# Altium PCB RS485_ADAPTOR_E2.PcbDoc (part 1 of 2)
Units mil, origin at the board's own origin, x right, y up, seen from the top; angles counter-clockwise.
Board outline 2150 x 1600 mil, 2 copper layers (Top Layer, Bottom Layer), stack 62 mil thick; 112 components, 44 nets, 256 pads, 64 vias.
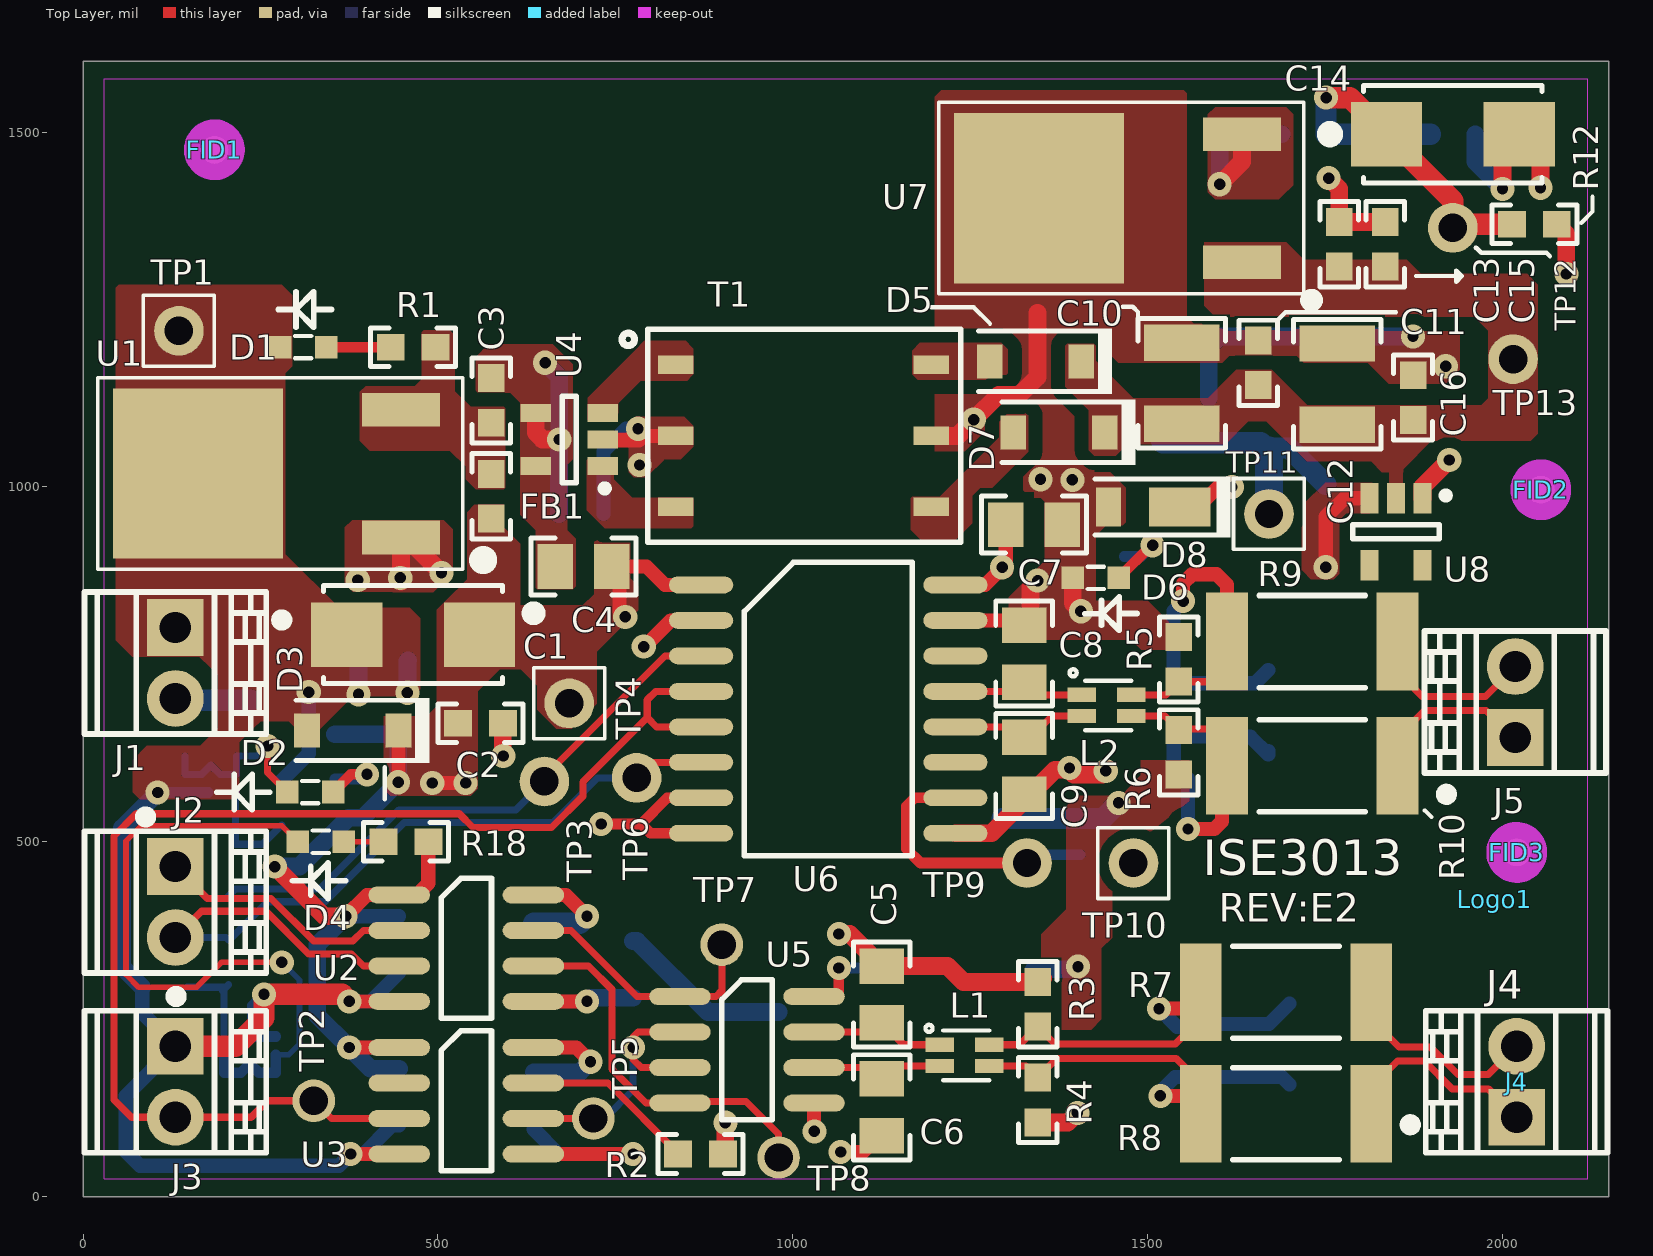
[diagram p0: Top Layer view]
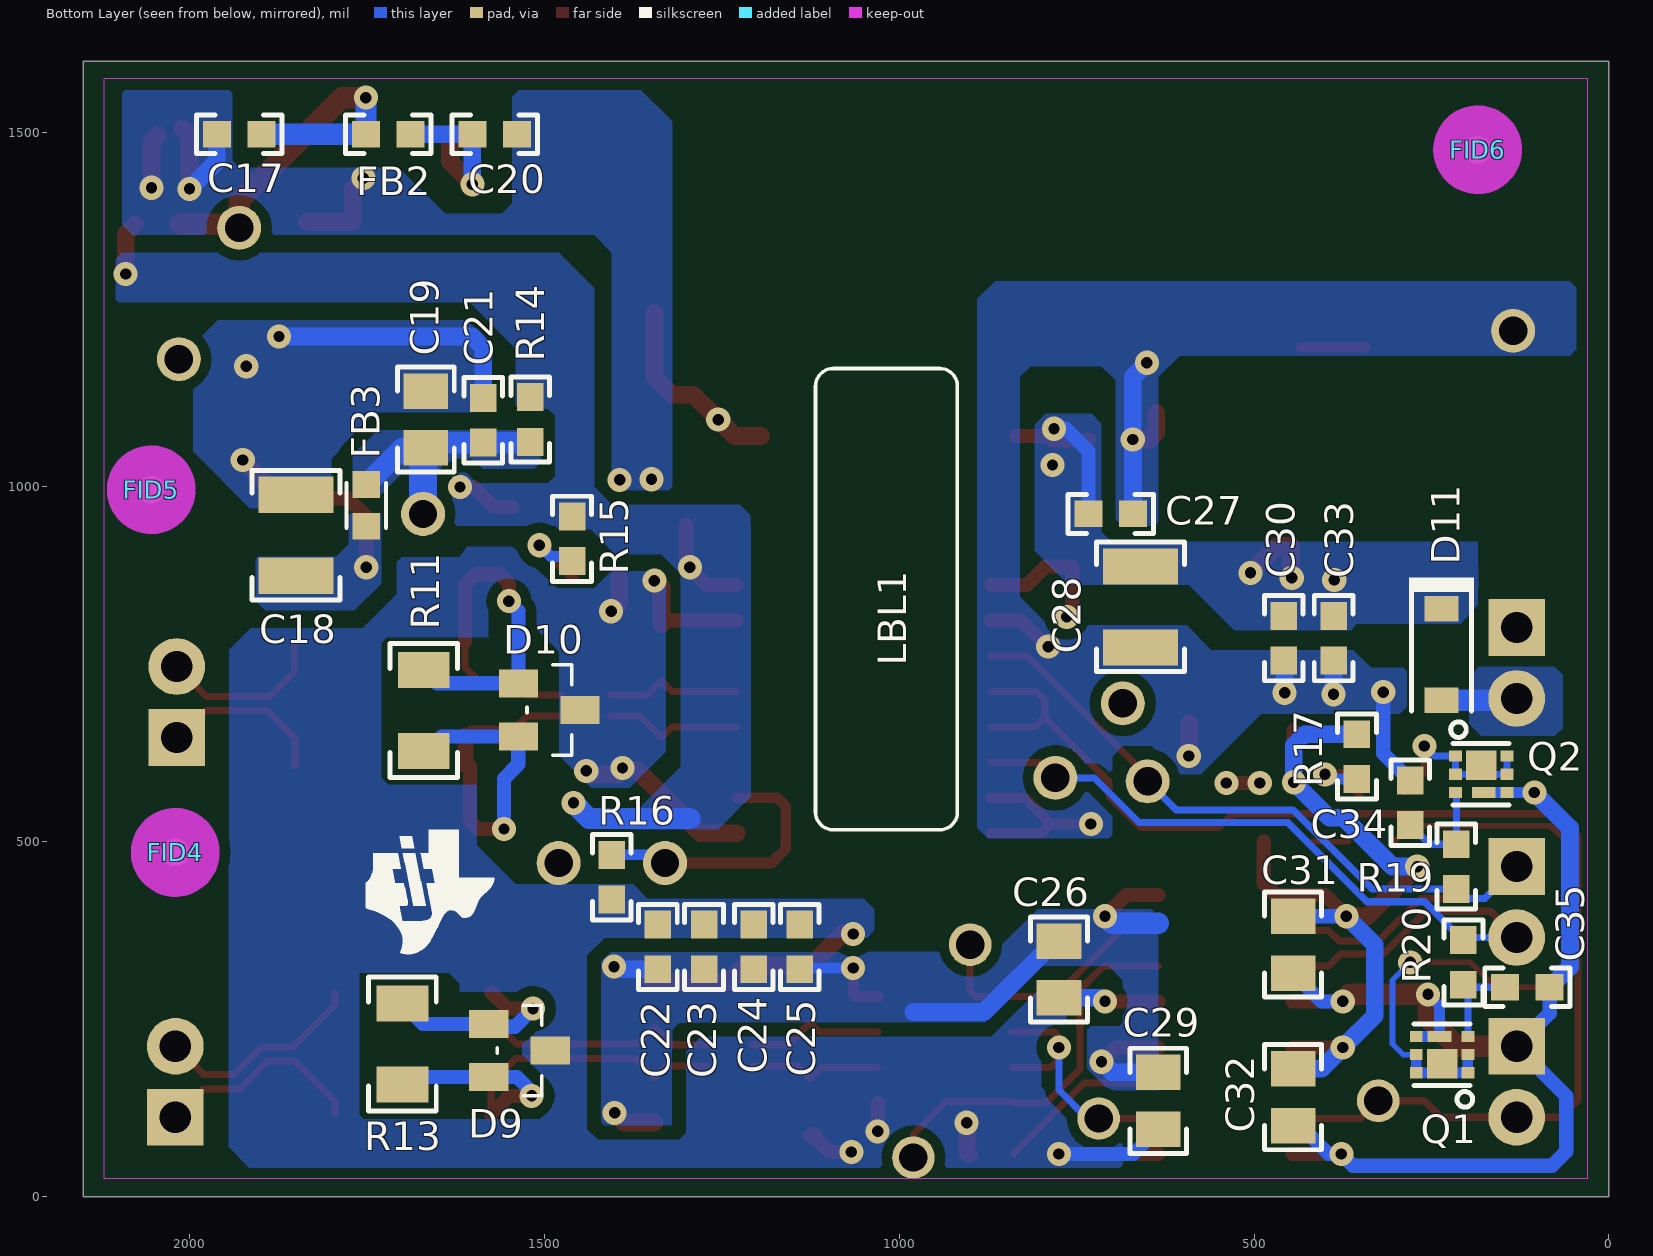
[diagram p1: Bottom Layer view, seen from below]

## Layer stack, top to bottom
Top Layer: signal copper 1.4
Dielectric: core 59.2, FR-4, Dk 4.8
Bottom Layer: signal copper 1.4

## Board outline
0,0 0,1600 2150,1600 2150,0

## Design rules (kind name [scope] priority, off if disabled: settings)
AcuteAngle [All] p1: minimum=4.50000000000000E+0001 checktracksonly=FALSE
AssemblyTestPointUsage [All] p1: valid=2
Clearance Clearance_TH [IsVia vs IsThruPin] p1: gap=10
Clearance "Clearance_SMT to Via" [IsSMTPin vs IsVia] p2: gap=8
Clearance "Clearance_Via to Via" [IsVia vs IsVia] p3: gap=8
Clearance "Clearance_Poly to Poly" [InPolygon vs InPolygon] p4: gap=20
Clearance Clearance_Poly [InPolygon] p5: gap=15
Clearance [All] p6: gap=8
ComponentClearance ComponentClearance_Logo [InComponentClass('Logo')] p1: gap=50 collisioncheckmode=3 verticalgap=10 showdistances=FALSE
ComponentClearance ComponentClearance_ScrewToNut [(HasFootprint('NY PMS 440 0025 PH')) vs (HasFootprint('Keystone_1902C'))] p2: gap=5 collisioncheckmode=3 verticalgap=10 showdistances=FALSE
ComponentClearance ComponentClearance_MountingHoles [InComponentClass('Mounting Holes')] p3: gap=250 collisioncheckmode=3 verticalgap=100000 showdistances=FALSE
ComponentClearance ComponentClearance_SmallPassives [HasFootprint('0201*') or HasFootprint('0402*') or HasFootprint('0508') or HasFootprint('0603*') or HasFootprint('0612') or HasFootprint('0805*') or HasFootprint('0815*') or HasFootprint('0830*') or HasFootprint('1206*') or HasFootprint('1210*') or HasFootprint('1808*') or HasFootprint('1812*') or HasFootprint('1825*') or HasFootprint('2010*') or HasFootprint('2220*') or HasFootprint('2225*') or HasFootprint('2512*') or HasFootprint('2728*') or HasFootprint('3518*') vs HasFootprint('0201*') or HasFootprint('0402*') or HasFootprint('0508') or HasFootprint('0603*') or HasFootprint('0612') or HasFootprint('0805*') or HasFootprint('0815*') or HasFootprint('0830*') or HasFootprint('1206*') or HasFootprint('1210*') or HasFootprint('1808*') or HasFootprint('1812*') or HasFootprint('1825*') or HasFootprint('2010*') or HasFootprint('2220*') or HasFootprint('2225*') or HasFootprint('2512*') or HasFootprint('2728*') or HasFootprint('3518*')] p4: gap=20 collisioncheckmode=3 verticalgap=10 showdistances=FALSE
ComponentClearance ComponentClearance_THtoSMT [IsThruComponent vs IsSMTComponent] p5: gap=100 collisioncheckmode=3 verticalgap=30 showdistances=FALSE
ComponentClearance ComponentClearance_THtoTH [IsThruComponent vs IsThruComponent] p6: gap=118.11 collisioncheckmode=3 verticalgap=30 showdistances=FALSE
ComponentClearance [All] p7: gap=40 collisioncheckmode=3 verticalgap=10 showdistances=FALSE
DiffPairsRouting [All] p1: maxlimit=100 minlimit=10 mostfreqgap=10 maxuncoupledlength=1000
FabricationTestPointUsage TestPointUsage [All] p1: valid=2 allowmultiple=FALSE
FabricationTestpoint Testpoint [All] p1: side=3 testpointundercomponent=TRUE minsize=40 maxsize=100 preferedsize=60 minholesize=0 maxholesize=40 preferedholesize=32 testpointgrid=1 allowsidetop=TRUE allowsidebottom=TRUE usegrid=TRUE gridtolerance=0.01
FanoutControl Fanout_LCC [IsLCC] p1: bgadir=Out bgaviamode=Centered fanoutstyle=Auto fanoutdirection=Alternating viagrid=1 // Fanout_LCC (Default Rule)
FanoutControl Fanout_BGA [IsBGA] p2: bgadir=Out bgaviamode=Centered fanoutstyle=Auto fanoutdirection=Alternating viagrid=1 // Fanout_BGA (Default Rule)
FanoutControl Fanout_Default [All] p4: bgadir=Out bgaviamode=Centered fanoutstyle=Auto fanoutdirection=Alternating viagrid=1 // Fanout_Default (Default Rule)
FanoutControl Fanout_Small [(CompPinCount < 5)] p5: bgadir=Out bgaviamode=Centered fanoutstyle=Auto fanoutdirection=OutThenIn viagrid=1 // Fanout_Small (Default Rule)
HoleSize [All] p1: absolutevalues=TRUE maxlimit=251 minlimit=8 maxpercent=80.000 minpercent=20.000
MinimumAnnularRing MinimumAnnularRing_ThermalPadVias [IsVia and InAnyComponent] p1: minimumring=5.91
MinimumAnnularRing [All] p2: minimumring=9
MinimumSolderMaskSliver MinimumSolderMaskSliver_Logo [InComponentClass('Logo') vs InComponentClass('Logo')] p1: minsoldermaskwidth=0.7
MinimumSolderMaskSliver [All] p2: minsoldermaskwidth=3.94
PlaneConnect [All] p1: planeconnectstyle=Relief reliefexpansion=10 reliefentries=4 reliefconductorwidth=10 reliefairgap=10
PolygonConnect [All] p1: connectstyle=Direct reliefconductorwidth=20 reliefentries=4 polygonreliefangle="45 Angle" airgapwidth=10
RoutingVias ThermalPadVias [IsVia and InAnyComponent] p1: holewidth=20 width=40 viastyle="Through Hole" minholewidth=16 minwidth=30 maxholewidth=20 maxwidth=40
RoutingVias [All] p2: holewidth=16 width=34 viastyle="Through Hole" minholewidth=12 minwidth=26 maxholewidth=20 maxwidth=40
SMDToCorner [All] p1: distance=30000
SilkToSilkClearance [All] p1: silktosilkclearance=5
SilkscreenOverComponentPads [All] p1: minsilkscreentomaskgap=5
SolderMaskExpansion [All] p1: expansion=2.5
Width [All] p1: maxlimit=200 minlimit=8 preferedwidth=10 checkconnectedcopper=TRUE
14 further rules are at their usual default settings.

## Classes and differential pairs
component class "Page4-DC-DC and Power supply": C10 C11 C12 C13 C14 C15 C16 C17 C18 C19 C20 C21 C27 C28 D5 D6 D7 D8 FB2 FB3 R12 R14 R15 T1 TP11 TP12 TP13 U4 U7 U8
component class "Page3-RS485 Transceivers": C1 C2 C3 C4 C5 C6 C7 C8 C9 C22 C23 C24 C25 C26 C29 C30 C31 C32 C33 C34 C35 D1 D2 D3 D4 D9 D10 D11 FB1 J1 J2 J3 J4 J5 L1 L2 Q1 Q2 R1 R2 R3 R4 R5 R6 R7 R8 R9 R10 R11 R13 R16 R17 R18 R19 R20 TP1 TP2 TP3 TP4 TP5 TP6 TP7 TP8 TP9 TP10 U1 U2 U3 U5 U6
component class AssemblyNote: ZZ1 ZZ2 ZZ3 ZZ4
component class FiducialMark: FID1 FID2 FID3 FID4 FID5 FID6
component class Label: LBL1
component class Page5-Hardware: !PCB1 FID1 FID2 FID3 FID4 FID5 FID6 LBL1 ZZ1 ZZ2 ZZ3 ZZ4

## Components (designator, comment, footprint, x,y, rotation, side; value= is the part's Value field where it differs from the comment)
C1 "293D475X9035C2TE3" 6032-28 465,791.85 r180 top (schematic designator C18)
C2 "C0603C104K5RACTU" 0603 560,666.85 r0 top (schematic designator C21)
C3 "C1608X7R1C105K" 0603 575,1121.85 r90 top (schematic designator C17)
C4 "08055C104KAT2A" 0805_HV 705,887.85 r180 top
C5 "08055A101JAT2A" 0805_HV 1125.5,284.85 r90 top
C6 "08055A101JAT2A" 0805_HV 1125.5,125.85 r270 top
C7 "08055C104KAT2A" 0805_HV 1340,946.85 r0 top (schematic designator C3)
C8 "08055A101JAT2A" 0805_HV 1326,765 r90 top (schematic designator C1)
C9 "08055A101JAT2A" 0805_HV 1326,607 r270 top (schematic designator C2)
C10 "" 1210 1548,1145.85 r90 top (schematic designator C13)
C11 "" 0603 1656,1174.85 r90 top (schematic designator C14)
C12 "" 1210 1767,1144.85 r270 top (schematic designator C22)
C13 "C0603C104K5RACTU" 0603 1770,1341.85 r90 top (schematic designator C26)
C14 "293D475X9035C2TE3" 6032-28 1930,1496.85 r0 top (schematic designator C27)
C15 "C1608X7R1C105K" 0603 1835,1341.85 r90 top (schematic designator C25)
C16 "" 0603 1874,1125.85 r90 top (schematic designator C24)
C17 "C0603C104K5RACTU" 0603 1930,1496.85 r0 bottom (schematic designator C29)
C18 "" 1210 1850,931.85 r270 bottom (schematic designator C23)
C19 "" 0805_HV 1667,1094.85 r270 bottom
C20 "C1608X7R1C105K" 0603 1570,1496.85 r180 bottom (schematic designator C28)
C21 "" 0603 1586,1093.85 r90 bottom (schematic designator C20)
C22 "C0603C106M9PACTU" 0603 1340,351.85 r90 bottom (schematic designator C9)
C23 "06033C104JAT2A" 0603 1275,351.85 r90 bottom (schematic designator C10)
C24 "06033C104JAT2A" 0603 1205,351.85 r90 bottom (schematic designator C11)
C25 "06033C104JAT2A" 0603 1140,351.85 r90 bottom (schematic designator C12)
C26 "08055C104KAT2A" 0805_HV 775,320 r270 bottom (schematic designator C31)
C27 "" 0603 702,961.85 r0 bottom (schematic designator C8)
C28 "" 1210 660,830.85 r90 bottom (schematic designator C7)
C29 "08055C104KAT2A" 0805_HV 635,135 r270 bottom (schematic designator C33)
C30 "C0603C104K5RACTU" 0603 458,786.85 r270 bottom (schematic designator C16)
C31 "08055C104KAT2A" 0805_HV 445,355 r270 bottom (schematic designator C30)
C32 "08055C104KAT2A" 0805_HV 445,140 r270 bottom
C33 "C1608X7R1C105K" 0603 388,786.85 r270 bottom (schematic designator C15)
C34 "06033C104JAT2A" 0603 280,555 r90 bottom (schematic designator C35)
C35 "06033C104JAT2A" 0603 115,295 r180 bottom (schematic designator C34)
D1 "LED_LG L29K-G2J1-24-Z" LED0603AA 310,1196.85 r0 top (schematic designator D6)
D2 "LED_LG L29K-G2J1-24-Z" LED0603AA 320,570 r0 top (schematic designator D11)
D3 "MMSZ5228B-7-F" sod-123 380,656.85 r180 top (schematic designator D8)
D4 "LED_LG L29K-G2J1-24-Z" LED0603AA 335,500 r0 top (schematic designator D10)
D5 "B0520LW-7-F" SOD-123 1342,1176.85 r180 top (schematic designator D3)
D6 "" LED0603AA 1427,871.85 r0 top (schematic designator D9)
D7 "B0520LW-7-F" SOD-123 1375,1076.85 r180 top (schematic designator D4)
D8 "" powerDI123 1495,971.85 r180 top (schematic designator D7)
D9 "SM712.TCT" SM712.TCT 1535,205.85 r270 bottom (schematic designator D2)
D10 "SM712.TCT" SM712.TCT 1493,685.83 r270 bottom (schematic designator D1)
D11 "B0520LW-7-F" SOD-123 236,764 r270 bottom (schematic designator D5)
FB1 "1000 OHM" 0603 575,986.85 r270 top
FB2 "1000 OHM" 0603 1720,1496.85 r0 bottom (schematic designator FB3)
FB3 "" FB0603 1751,973.85 r90 bottom (schematic designator FB2)
FID1 "Fiducial" Fiducial10-20 185,1475 r90 top (schematic designator FID3)
FID2 "Fiducial" Fiducial10-20 2054,996 r90 top (schematic designator FID1)
FID3 "Fiducial" Fiducial10-20 2020,485 r90 top (schematic designator FID2)
FID4 "Fiducial" Fiducial10-30 2020,485 r90 bottom (schematic designator FID5)
FID5 "Fiducial" Fiducial10-30 2054,996 r90 bottom (schematic designator FID6)
FID6 "Fiducial" Fiducial10-30 185,1475 r90 bottom (schematic designator FID4)
J1 "CON-OSTVN02A150" CN2_MTB_P100_PD80_D1.1_S5.54X6.5_STACK 130,751.85 r270 top (schematic designator J7)
J2 "CON-OSTVN02A150" CN2_MTB_P100_PD80_D1.1_S5.54X6.5_STACK 130,415 r270 top (schematic designator J1)
J3 "CON-OSTVN02A150" CN2_MTB_P100_PD80_D1.1_S5.54X6.5_STACK 130,161.85 r270 top
J4 "CON-OSTVN02A150" CN2_MTB_P100_PD80_D1.1_S5.54X6.5_STACK 2020,161.85 r90 top (schematic designator J6)
J5 "CON-OSTVN02A150" CN2_MTB_P100_PD80_D1.1_S5.54X6.5_STACK 2018,696.85 r90 top (schematic designator J2)
L1 "ACM2012-201-2P-T002" IND_0805-4P 1242,199 r0 top (schematic designator L2)
L2 "ACM2012-201-2P-T002" IND_0805-4P 1442,692 r0 top (schematic designator L1)
LBL1 "Size: 0.65\" x 0.20 \"" Label_650x200 1018,841.85 r90 bottom
Logo1 "Texas Instruments" TI_Stacked_SolderMask_Small 1989,419 r0 top
Q1 "CSD17571Q2" SON_CSD17571Q2 235,200 r90 bottom
Q2 "CSD17571Q2" SON_CSD17571Q2 180,595 r270 bottom
R1 "CRCW0603300RJNEA" 0603 465,1196.85 r0 top (schematic designator R7)
R2 "CRCW06034K70JNEA" 0603 870,60 r180 top (schematic designator R15)
R3 "CRCW06034K70JNEA" 0603 1345,271 r270 top (schematic designator R12)
R4 "CRCW06034K70JNEA" 0603 1345,136 r270 top (schematic designator R11)
R5 "CRCW06034K70JNEA" 0603 1544,757 r270 top (schematic designator R10)
R6 "CRCW06034K70JNEA" 0603 1544,626 r270 top (schematic designator R9)
R7 "ERJ-1TYJ100U" 2512M 1695,287.85 r0 top (schematic designator R5)
R8 "ERJ-1TYJ100U" 2512M 1695,116.85 r0 top (schematic designator R4)
R9 "ERJ-1TYJ100U" 2512M 1732,782 r0 top (schematic designator R2)
R10 "ERJ-1TYJ100U" 2512M 1732,607 r0 top (schematic designator R1)
R11 "RC1206FR-07120RL" 1206 1670,685 r90 bottom (schematic designator R3)
R12 "CRCW06030000Z0EA" 0603 2045,1370 r0 top (schematic designator R14)
R13 "RC1206FR-07120RL" 1206 1700,215 r90 bottom (schematic designator R6)
R14 "CRCW06030000Z0EA" 0603 1520,1095 r90 bottom (schematic designator R13)
R15 "" 0603 1461,926.85 r90 bottom (schematic designator R8)
R16 "CRCW06030000Z0EA" 0603 1405,450 r270 bottom (schematic designator R20)
R17 "CRCW0603300RJNEA" 0603 355,620 r90 bottom
R18 "CRCW0603300RJNEA" 0603 455,500 r0 top (schematic designator R16)
R19 "CRCW0603300RJNEA" 0603 215,465 r90 bottom
R20 "CRCW0603300RJNEA" 0603 205,330 r270 bottom (schematic designator R18)
T1 "TRNSFMR 760390014" 760390015 835,1171.85 r0 top
TP1 "TP-040_RND" TP-040_RND#1 135,1220 r0 top (schematic designator TP4)
TP2 "TP-040_RND" TP-040_RND#2 325,135 r90 top (schematic designator TP11)
TP3 "TP-040_RND" TP-040_RND#1 650,585 r90 top (schematic designator TP6)
TP4 "TP-040_RND" TP-040_RND#1 685,695 r180 top (schematic designator TP1)
TP5 "TP-040_RND" TP-040_RND#3 719,110 r90 top (schematic designator TP10)
TP6 "TP-040_RND" TP-040_RND#1 780,590 r90 top (schematic designator TP7)
TP7 "TP-040_RND" TP-040_RND#4 900,355 r90 top (schematic designator TP8)
TP8 "TP-040_RND" TP-040_RND#4 980,55 r90 top (schematic designator TP9)
TP9 "TP-040_RND" TP-040_RND#1 1330,470 r90 top (schematic designator TP12)
TP10 "TP-040_RND" TP-040_RND#1 1480,470 r0 top (schematic designator TP3)
TP11 "" TP-040_RND#1 1671,961.85 r180 top (schematic designator TP2)
TP12 "TP-040_RND" TP-040_RND#1 1930,1365 r0 top (schematic designator TP5)
TP13 "TP-040_RND" TP-040_RND#1 2015,1180 r90 top
U1 "TPS7A6533QKVURQ1" KVU_1 305,1018.85 r90 top (schematic designator U5)
U2 "ISO7221AD" D0008A_N 540,350 r0 top (schematic designator U7)
U3 "ISO7221AD" D0008A_N 540,135 r0 top (schematic designator U8)
U4 "SN6501DBV" DBV0005A_N 685,1066.85 r180 top (schematic designator U3)
U5 "SN65HVD3082ED" D0008A_N 935.5,206.85 r0 top (schematic designator U2)
U6 "ISO3088DW" DW0016A_N 1050,686.85 r0 top (schematic designator U1)
U7 "TPS7A6533QKVURQ1" KVU_1 1490,1406.85 r90 top (schematic designator U6)
U8 "TLV70450DBV" DBV0005A_N 1850,936.85 r270 top (schematic designator U4)
ZZ1 "These assemblies must comply with workmanship standards IPC-A-610 Class 2, unless otherwise specified." AssemblyNote 341,2193.85 r0 top (schematic designator ZZ4)
ZZ2 "This Assembly Note is for PCB labels only" AssemblyNoteLabel 342,2294.85 r0 top (schematic designator ZZ1)
ZZ3 "These assemblies must be clean and free from flux and all contaminants. Use of no clean flux is not acceptable." AssemblyNote 342,2097.85 r0 top
ZZ4 "These assemblies are ESD sensitive, ESD precautions shall be observed." AssemblyNote 341,2017 r0 top

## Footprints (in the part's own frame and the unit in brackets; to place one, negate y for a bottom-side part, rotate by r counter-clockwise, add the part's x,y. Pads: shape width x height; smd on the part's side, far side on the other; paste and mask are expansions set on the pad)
0603 [mm]
  rect 1x0.95 smd: 1(-0.8,0) 2(0.8,0)
  silkscreen extent -1.52,-0.69 1.52,0.69, body extent -0.87,-0.47 0.87,0.47, height 0.85
0805_HV [mil] "0805 with 30mil clearance between pads"
  rect 50x63 smd: 1(-40,0) 2(40,0)
  silkscreen extent -74,-40 74,40, body extent -43,-29 43,29, height 43
1206 [mm] "1206 from SM-752 data"
  rect 1.3x1.85 smd: 1(-1.45,0) 2(1.45,0)
  silkscreen extent -2.4,-1.21 2.4,1.21, body extent -1.7,-0.9 1.7,0.9, height 1.35
1210 [mm]
  rect 1.3x2.7 smd: 1(-1.45,0) 2(1.45,0)
  silkscreen extent -2.32,-1.57 2.32,1.57, body extent -1.7,-1.35 1.7,1.35, height 1.35
2512M [mm] "Chip Resistor, Body 6.3x3.2mm, IPC Low Density"
  rect 1.5x3.5 smd: 1(-3.05,0) 2(3.05,0)
  silkscreen extent -1.9,-1.65 1.9,1.65, body extent -3.22,-1.67 3.22,1.67, height 0.71
6032-28 [mm]
  rect 2.55x2.3 smd: 1(-2.375,0) 2(2.375,0)
  silkscreen extent -4.42,-1.75 3.2,1.75, body extent -3.15,-1.75 3.15,1.75, height 2.8
760390015 [mm]
  rect 1.27x0.66 smd: 1(0,0) 2(0,-2.54) 3(0,-5.08) 4(9.14,-5.08) 5(9.14,-2.54) 6(9.14,0)
  silkscreen extent -1.92,-6.35 10.2,1.27, body extent -1,-6.4 10.2,1.2, height 4.2
AssemblyNote [mil] "Assembly Note"
AssemblyNoteLabel [mil] "Assembly Note for PCB Labels"
CN2_MTB_P100_PD80_D1.1_S5.54X6.5_STACK [mil]
  rect 80x80 / inner round 80 / far side rect 80x80 hole 44: 1(-50,0)
  round 80 hole 44: 2(50,0)
  silkscreen extent -100,-128 100,160
D0008A_N [mm] "SOIC, 8-Leads, Body 4.9x3.9mm, Pitch 1.27mm, IPC Medium Density"
  oval 2.2x0.6 smd: 1(-2.4,1.905) 2(-2.4,0.635) 3(-2.4,-0.635) 4(-2.4,-1.905) 5(2.4,-1.905) 6(2.4,-0.635) 7(2.4,0.635) 8(2.4,1.905)
  silkscreen extent -0.9,-2.5 0.9,2.5, body extent -3,-2.45 3,2.45, height 1.63
DBV0005A_N [mm]
  rect 1.1x0.65 smd: 1(-1.2,0.95) 2(-1.2,0) 3(-1.2,-0.95) 4(1.2,-0.95) 5(1.2,0.95)
  silkscreen extent -1.4,-1.55 0.25,1.88, body extent -1.42,-1.46 1.42,1.46, height 1.08
DW0016A_N [mm] "SOIC, 16-Leads, Body 10.3x7.5mm, Pitch 1.27mm, IPC Medium Density"
  oval 2.3x0.6 smd: 1(-4.55,4.445) 2(-4.55,3.175) 3(-4.55,1.905) 4(-4.55,0.635) 5(-4.55,-0.635) 6(-4.55,-1.905) 7(-4.55,-3.175) 8(-4.55,-4.445) 9(4.55,-4.445) 10(4.55,-3.175) 11(4.55,-1.905) 12(4.55,-0.635) 13(4.55,0.635) 14(4.55,1.905) 15(4.55,3.175) 16(4.55,4.445)
  silkscreen extent -3,-5.25 3,5.25, body extent -5.14,-5.13 5.14,5.13, height 2.5
FB0603 [mm]
  rect 0.95x1 smd: 1(-0.75,0) 2(0.75,0)
  silkscreen extent -0.8,-0.7 0.8,0.7
Fiducial10-20 [mm]
  round 1 smd mask+0.5: 1(0,0)
  Top Layer keep-out circle w1.178: c0,0 r0.5
Fiducial10-30 [mm]
  round 1 smd mask+1: 1(0,0)
  Top Layer keep-out circle w1.678: c0,0 r0.75
IND_0805-4P [mil]
  rect 40x20 smd: 1(-35,15) 2(-35,-15) 3(35,-15) 4(35,15)
  silkscreen extent -55,-35 35,43
KVU_1 [mm]
  rect 1.2x2.8 smd: 1(-2.29,-3.635) 3(2.29,-3.635)
  rect 6.096x6.096 smd: 2(0,3.635)
  silkscreen extent -3.43,-6.63 3.43,7.22
Label_650x200 [mil] "Thermal Transfer Label"
  round 1 on Mech14: 0(0,0)
  silkscreen extent -325,-100 325,100, body extent -326,-101 326,101, height 1
LED0603AA [mil]
  rect 32x32 smd: 1(-32.48,0) 2(32.48,0)
  silkscreen extent -35,-16 40,78
powerDI123 [mm]
  rect 2.2x1.4 smd: 1(-1.275,0)
  rect 0.9x1.4 smd: 2(1.275,0)
  silkscreen extent -3.1,-1.09 1.76,1.09, body extent -2.37,-0.96 1.53,0.97, height 1
SM712.TCT [mm]
  rect 1x1.4 smd: 1(-0.95,-1.1) 2(0.95,-1.1) 3(0,1.1)
  silkscreen extent -1.62,-0.8 1.62,0.8, body extent -1.5,-1.32 1.5,1.32, height 1.08
sod-123 [mm]
  rect 0.915x1.22 smd: 1(-1.637,0) 2(1.637,0)
  silkscreen extent -2.74,-1.17 2.03,1.17, body extent -1.93,-0.9 1.93,0.9, height 1.35
SOD-123 [mm]
  rect 0.915x1.22 smd: 1(-1.637,0) 2(1.637,0)
  silkscreen extent -2.74,-1.17 2.03,1.17, body extent -1.93,-0.9 1.93,0.9, height 1.35
SON_CSD17571Q2 [mm] "SON, MOSFET, N-CH, 30V, 22A, SON 2X2 MM"
  rect 0.4x0.455 smd mask+0.038: 1(-0.65,-0.923) 2(0,-0.923) 5(0,0.923) 6(-0.65,0.923)
  rect 0.4x0.455 smd: 3(0.65,-0.923) 4(0.65,0.923)
  rect 0.4x0.85 smd mask+0.038: 7(0.65,0.096)
  rect 1.05x1.1 smd mask+0.038: 8(-0.325,0)
  silkscreen extent -1.88,-1.09 1.1,1, body extent -1,-1 1,0.97, height 0.85
TI_Stacked_SolderMask_Small [mil]
TP-040_RND#1 [mil]
  round 70 / inner round 62 / far side round 62 hole 40: 1(0,0)
  silkscreen extent -50,-50 50,50
TP-040_RND#2 [mil]
  round 60 hole 40 paste+0: 1(0,0)
TP-040_RND#3 [mil]
  round 60 / inner oval 60x62 / far side round 60 hole 40: 1(0,0)
TP-040_RND#4 [mil]
  round 60 hole 40: 1(0,0)

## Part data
C1 C14: "CAP, TA, 4.7uF, 35V, +/-10%, 1.9 ohm, SMD"
C2 C13 C17 C30: "CAP, CERM, 0.1uF, 50V, +/-10%, X7R, 0603"
C3 C15 C20 C33: "CAP, CERM, 1uF, 16V, +/-10%, X7R, 0603"
C4 C7 C26 C29 C31 C32: "CAP, CERM, 0.1uF, 50V, +/-10%, X7R, 0805"
C5 C6 C8 C9: "CAP, CERM, 100pF, 50V, +/-5%, C0G/NP0, 0805"
C10 C12 C18 C28: library part GMK325AB7106MM-T, "CAP, CERM, 10uF, 35V, +/-20%, X7R, 1210"
C11 C16 C21 C27: library part C0603C104K5RACTU, "CAP, CERM, 0.1uF, 50V, +/-10%, X7R, 0603"
C19: library part C2012X5R1H475K125AB, "CAP, CERM, 4.7uF, 50V, +/-10%, X5R, 0805"
C22: "CAP, CERM, 10uF, 6.3V, +/-20%, X5R, 0603"
C23 C24 C25 C34 C35: "CAP, CERM, 0.1uF, 25V, +/-5%, X7R, 0603"
D1 D2 D4: "LED SmartLED Green 570NM"
D3: library part 1SMB5915BT3G, "DIODE ZENER 3.9V 500MW SOD123"
D5 D7 D11: library part MBR0520LT1G, "Diode, Schottky, 20V, 0.5A, SOD-123"
D6: library part "LED_LG L29K-G2J1-24-Z", "LED SmartLED Green 570NM"
D8: library part DFLZ6V2-7, "Diode, Zener, 6.2V, 1W, PowerDI123"
D9 D10: "IC TVS ASYMM RS-485V 7/12V SOT23"
FB1 FB2 FB3: library part MMZ1608B102C, "FERRITE CHIP 1000 OHM 300MA 0603"
FID1 FID2 FID3 FID4 FID5 FID6: "Fiducial mark.  There is nothing to buy or mount."
J1: "CONN TERM BLOCK 2.54MM 2POS PCB"
J2 J3 J4 J5: "Terminal Block, 4x1, 2.54mm, TH"
L1 L2: library part IND_ACM2012_SERIES, "CHOKE COMM MODE 200 OHM .35A SMD"
LBL1: library part THT-14-423-10, "Thermal Transfer Printable Labels, 0.650\" W x 0.200\" H - 10,000 per roll"
Logo1: library part TI_Logo, "Texas Instrument Corporate Signature"
Q1 Q2: "MOSFET, N-CH, 30V, 22A, SON 2X2 MM"
R1 R17 R18 R19 R20: "RES, 300 ohm, 5%, 0.1W, 0603"
R2 R3 R4 R5 R6: "RES, 4.7k ohm, 5%, 0.1W, 0603"
R7 R8 R9 R10: "RES, 10 ohm, 5%, 1W, 2512"
R11 R13: "RES, 120 ohm, 1%, 0.25W, 1206"
R12 R14 R16: "RES, 0 ohm, 5%, 0.1W, 0603"
R15: library part CRCW06033K90JNEA, "RES, 3.9k ohm, 5%, 0.1W, 0603"
T1: library part "TRNSFMR 760390015", "Transformer 475uH SMD"
TP1 TP2 TP3 TP4 TP5 TP6 TP7 TP8 TP9 TP10 TP12 TP13: "Test Point, O.040 Hole"
TP11: library part TP-040_RND, "Test Point, O.040 Hole"
U1 U7: "IC, 300-mA 40-V LOW-DROPOUT REGULATOR WITH 25-uA QUIESCENT CURRENT"
U2 U3: "1 Mbps Dual Channels, 1 / 1, Digital Isolator, 3.3 V / 5 V, -40 to +125 degC, 8-pin SOIC (D), Green (RoHS & no Sb/Br)"
U4: "Transformer Driver for Isolated Power Supplies, DBV0005A"
U5: "IC, RS485 TRANSCEIVER LP, 8-SOIC"
U6: "Isolated RS-485 Transceiver, 20 Mbps, 5 V, Half Duplex, -40 to 85 degC, 16-pin SOIC (DW)"
U8: "Regulator, LDO, 5V, 0.15A, SOT23-5"
ZZ1 ZZ3 ZZ4: library part AssemblyNote
ZZ2: library part AssemblyNoteLabel

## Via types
v1: diameter 34, hole 16, Top Layer to Bottom Layer, tented both sides, 64 vias

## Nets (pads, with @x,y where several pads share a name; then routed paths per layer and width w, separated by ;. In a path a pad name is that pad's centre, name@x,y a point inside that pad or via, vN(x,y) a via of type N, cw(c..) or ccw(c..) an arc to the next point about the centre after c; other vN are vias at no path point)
+5.0V_VDC: C7.1 C22.1 C23.1 C24.1 C25.1 C26.1 C29.1 D8.1 R4.2 R6.2 R12.2 R14.2 R15.2 U2.8 U3.8 U5.8 U6.16 | length 1330.7
  Top Layer w15: U5.8@1029.98,281.85 1061.85,281.85 1065,285 v1(1065,322)
  Top Layer w20: U3.8@634.49,210 695,210 v1(715,190) ; U2.8@634.49,425 680,425 v1(710,395) ; U6.16@1229.13,861.85 1271,861.85 1295.5,886.35 1300,881.85 C7.1@1300,946.85 ; D8.1@1545.2,971.85 1571,971.85 1599,999.85 v1(1619,999.85)
  Top Layer w25: R4.2@1345,104.5 1387.5,104.5 v1(1401,118) ; R12.2@2076.5,1370 2090,1356.5 v1(2090,1300)
  Bottom Layer w15: v1(1065,322) 1138.35,322 C25.1@1140,320.35
  Bottom Layer w25: C29.1@635,175 700,175 v1(715,190) ; C26.1@775,360 780.49,360 880.49,260 980,260 ; C22.1@1340,320.35 v1@1389.65,320.35
  Bottom Layer w30: 635,385 700,385 v1(710,395) ; 1295,532.85 1437,532.85 v1(1459,554.85)
  other v1: 1402,324 1295,886.85
+5V: C27.2 C28.2 C30.1 C33.1 D11.1 T1.2 U1.1 U4.2 | length 378.2
  Top Layer w20: U4.2@732.24,1066.85 733.24,1065.85 783,1065.85 789,1071.85 T1.2@835,1071.85
  Top Layer w25: v1@448.11,866.74 448.11,916.69 467.16,916.69 v1(505,878.85)
  Bottom Layer w20: C27.2@733.5,961.85 733.5,1050.35 765,1081.85 v1(782,1081.85)
  other v1: 387,868.85 447,871.85 784,1030.85
+6V_VDC: C10.1 C11.1 C12.2 C13.1 C15.1 C16.1 D5.1 D7.1 TP13.1 U7.1 U8.2
DGND: C1.2 C2.2 C3.2 C4.2 C27.1 C28.1 C30.2 C31.2 C32.2 C33.2 C34.2 C35.2 D1.1 D3.2 J1.1 J3.1 Q1.4 Q1.7 Q2.4 Q2.7 TP1.1 U1.2 U2.4 U3.4 U4.4 U4.5 U6.2 U6.7 U6.8 | length 2609.5
  Top Layer w15: v1(730,525) 786.42,525 ; U6.8@870.87,511.85 799.57,511.85 786.42,525 ; U6.7@870.87,561.85 823.27,561.85 786.42,525
  Top Layer w20: v1(375,275) U2.4@445.51,275 ; v1(377,60) U3.4@445.51,60 ; v1(790,774.85) 790,773.85 828,811.85 U6.2@870.87,811.85
  Top Layer w25: C2.2@591.5,666.85 591.5,621.35 v1(592,620.85) ; U4.4@637.76,1104.25 637.76,1076.61 647.51,1066.85 v1(671,1066.85)
  Top Layer w30: J3.1@130,211.85 214.85,211.85 255,252 v1(255,285) 365,285 v1(375,275)
  Bottom Layer w15: v1(105,569.41) Q2.4@143.68,569.41 Q2.7@176.22,569.41 ; v1(255,285) 238.78,268.78 Q1.7@238.78,225.59 Q1.4@271.32,225.59
  Bottom Layer w20: C35.2@83.5,295 83.5,258.35 J3.1@130,211.85 60,141.85 60,63.5 80,43.5 360.5,43.5 v1(377,60) 395,60 435,100 C32.2@445,100 ; C34.2@280,586.5 318,624.5 v1(318,710.85) ; v1(375,275) 405,275 C31.2@445,315
  Bottom Layer w25: C35.2@83.5,295 55,323.5 55,519.41 v1(105,569.41) ; v1(388,707.85) C33.2@388,755.35 ; v1(457,709.85) 457,754.35 C30.2@458,755.35 ; v1(651,1174.85) 671,1154.85 v1(671,1066.85) v1@670.5,1066.35 ; v1@669,1064.85 v1@670.5,1066.35 ; C27.1@670.5,961.85 v1@670.5,1066.35
DIR: J3.2 TP2.1 U3.3 U6.4 U6.5 | length 1839.3
  Top Layer w10: U3.3@445.51,110 350,110 TP2.1@325,135 260,135 236.85,111.85 J3.2@130,111.85 68.15,111.85 43.5,136.5 43.5,507.91 75,539.41 530,539.41 549.41,520 660.15,520 704.15,564 704.15,584.15 795,675 ; U6.5@870.87,661.85 808.15,661.85 795,675 ; U6.4@870.87,711.85 806.85,711.85 795,700 795,675
DVCC: C1.1 C2.1 C4.1 C31.1 C32.1 D3.1 FB1.2 R17.2 R18.2 TP4.1 U2.1 U3.1 U6.1 | length 1463.8
  Top Layer w20: v1(370,395) 400,425 U2.1@445.51,425 470,425 486.5,441.5 R18.2@486.5,500 ; v1(375,210) U3.1@445.51,210 ; v1(444,583.85) 444.47,584.32 D3.1@444.47,656.85 ; v1(492,582.85) v1(539,582.85) ; v1(764,816.85) 756,824.85 756,887.85 794,887.85 820,861.85 U6.1@870.87,861.85
  Top Layer w25: v1(270,465) 340,395 v1(370,395)
  Bottom Layer w20: v1(370,395) C31.1@445,395 ; v1@491,583.85 v1(492,582.85)
  Bottom Layer w25: v1(270,465) 305,465 373.93,533.93 394.07,533.93 v1(444,583.85) 444,636 428.5,651.5 R17.2@355,651.5 ; v1(370,395) 330,355 330,255 v1(375,210) 405,180 C32.1@445,180
GND_VDC: C5.2 C6.2 C7.2 C8.2 C9.2 C10.2 C11.2 C12.1 C13.2 C14.2 C15.2 C16.2 C17.2 C18.1 C19.1 C20.2 C21.2 C22.2 C23.2 C24.2 C25.2 C26.2 C29.2 D6.1 D8.2 D9.3 D10.3 R2.1 R3.1 R5.1 R16.2 T1.5 TP10.1 U2.5 U3.5 U5.5 U6.9 U6.15 U7.2 U8.1 | length 2482
  Top Layer w20: U3.5@634.49,60 v1(775,60) ; U2.5@634.49,275 v1(710,275) ; U5.5@1029.98,131.85 1029.98,92.36 v1(1030.5,91.85) ; v1(1067.5,62.85) 1098.5,62.85 1121.5,85.85 C6.2@1125.5,85.85 ; U6.15@1229.13,811.85 1330,811.85 C8.2@1335,806.85
  Top Layer w25: R2.1@901.5,60 905,63.5 v1(905,104) ; v1(1065,370) 1080.35,370 C5.2@1125.5,324.85 1218.15,324.85 1240.5,302.5 R3.1@1345,302.5 ; C6.2@1120,85.85 C6.2@1121.5,85.85 ; T1.5@1194.84,1071.85 1232,1071.85 v1(1255,1094.85) 1290.15,1130 1320,1130 1345,1155 1345,1245 ; U6.9@1229.13,511.85 1280,511.85 1335,566.85 1369.5,601.35 1387.5,601.35 v1(1390,603.85) ; C8.2@1335,806.85 1335,857.85 v1(1345,867.85) v1@1345,868.85 ; R3.1@1345,307.5 R3.1@1352.47,307.5 ; D6.1@1394.52,871.85 1394.52,836.33 v1(1406,824.85) ; v1@1396,594.85 1436,594.85 v1(1441,599.85) ; v1(1755,1435) 1770,1420 C13.2@1770,1373.35 C15.2@1835,1373.35 ; U8.1@1887.4,984.09 1887.4,1000.25 v1(1925,1037.85) ; v1(2000,1420) 2000,1495 C14.2@2010,1505 ; C14.2@2045,1495 2053.5,1486.5 v1(2053.5,1421.5)
  Bottom Layer w20: C29.2@635,95 670,60 v1(775,60)
  Bottom Layer w25: v1(710,275) 715,280 C26.2@775,280 ; v1@1405,823.85 v1(1406,824.85) ; C21.2@1586,1125.35 1586,1196 1601.85,1211.85 v1(1874,1211.85) ; C17.2@1961.5,1496.85 1961.5,1458.5 v1(2000,1420)
  other v1: 1394,1009.85 1349,1010.85 1920,1170
NetC3_1: C3.1 FB1.1 R1.2 U1.3
NetC5_1: C5.1 L1.1 U5.7 | length 195.2
  Top Layer w10: U5.7@1029.98,231.85 1112.5,231.85 C5.1@1125.5,244.85 1156.35,214 L1.1@1207,214
NetC6_1: C6.1 L1.2 U5.6 | length 191.2
  Top Layer w10: U5.6@1029.98,181.85 1109.5,181.85 C6.1@1125.5,165.85 1143.65,184 L1.2@1207,184
NetC8_1: C8.1 L2.1 U6.13 | length 192.3
  Top Layer w10: U6.13@1229.13,711.85 1320,711.85 1335,726.85 1354.85,707 L2.1@1407,707
NetC9_1: C9.1 L2.2 U6.12 | length 196.6
  Top Layer w10: U6.12@1229.13,661.85 1320,661.85 1335,646.85 1365.15,677 L2.2@1407,677
NetC14_1: C14.1 C17.1 FB2.2 R12.1 TP12.1 | length 561.2
  Top Layer w30: v1(1751.5,1548.5) 1784.84,1548.5 C14.1@1836.5,1496.85 1930,1403.35 TP12.1@1930,1365 1935,1370 R12.1@2013.5,1370
  Bottom Layer w30: v1(1751.5,1548.5) FB2.2@1751.5,1496.85 C17.1@1898.5,1496.85
NetC18_2: C18.2 FB3.1 U8.3 | length 143.5
  Top Layer w20: v1(1751,886.85) 1751,957.85 1777.24,984.09 U8.3@1812.6,984.09
NetC19_2: C19.2 C21.1 FB3.2 R14.1 TP11.1 | length 350.6
  Bottom Layer w30: R14.1@1520,1063.5 1521.15,1062.35 C21.1@1586,1062.35 1659.5,1062.35 C19.2@1667,1054.85 ; C19.2@1671,1050.85 C19.2@1667,1054.85 ; FB3.2@1751,1003.38 1699.53,1054.85 C19.2@1667,1054.85
  Bottom Layer w40: TP11.1@1671,961.85 C19.2@1671,1050.85
NetC20_1: C20.1 FB2.1 U7.3 | length 241
  Top Layer w25: v1(1601.5,1426.5) 1633.11,1458.11 U7.3@1633.11,1497.01
  Bottom Layer w25: v1(1601.5,1426.5) C20.1@1601.5,1496.85 FB2.1@1688.5,1496.85
NetC34_1: C34.1 Q2.3 R19.2 | length 149.6
  Bottom Layer w10: Q2.3@216.32,569.41 215,568.09 R19.2@215,496.5 252.99,496.5 C34.1@280,523.5
NetC35_1: C35.1 Q1.3 R20.2 | length 133.6
  Bottom Layer w10: C35.1@146.5,295 R20.2@201.5,295 ; R20.2@196.5,290 R20.2@198.68,292.19 ; Q1.3@198.68,225.59 R20.2@198.68,292.19 ; R20.2@205,298.5 R20.2@201.5,295 ; R20.2@198.68,292.19 R20.2@201.5,295
NetD1_2: D1.2 R1.1 | length 91
  Top Layer w15: D1.2@342.48,1196.85 R1.1@433.5,1196.85
NetD2_1: D2.1 Q2.1 Q2.2 Q2.5 Q2.6 Q2.8 | length 260.5
  Top Layer w10: v1(260,635) 260,597.52 D2.1@287.52,570
  Bottom Layer w10: Q2.6@143.68,620.59 Q2.5@143.68,595 167.2,595 Q2.8@180,607.8 192.8,595 Q2.2@216.32,595 Q2.1@216.32,620.59 245.59,620.59 v1(260,635)
NetD2_2: D2.2 R17.1 | length 105.6
  Top Layer w15: D2.2@352.48,570 377.48,595 v1(400,595)
  Bottom Layer w15: R17.1@355,588.5 393.5,588.5 v1(400,595)
NetD4_1: D4.1 Q1.1 Q1.2 Q1.5 Q1.6 Q1.8 | length 989.4
  Top Layer w8: v1(280,330) 195,330 160,295 78.22,295 60.5,312.72 60.5,500.87 82.04,522.41 280.11,522.41 D4.1@302.52,500
  Bottom Layer w8: Q1.5@271.32,200 290,200 305,215 305,305 v1(280,330)
  Bottom Layer w15: Q1.2@198.68,200 Q1.1@198.68,174.41 222.2,174.41 Q1.8@235,187.2 247.8,174.41 Q1.6@271.32,174.41 Q1.5@271.32,200
NetD4_2: D4.2 R18.1 | length 56
  Top Layer w8: D4.2@367.48,500 R18.1@423.5,500
NetD5_2: D5.2 T1.6
NetD6_2: D6.2 R15.1 | length 113.2
  Top Layer w15: D6.2@1459.48,871.85 1505.48,917.85 v1(1507,917.85)
  Bottom Layer w15: R15.1@1467,901.85 1491,901.85 v1(1507,917.85)
NetD7_2: D7.2 T1.4
NetD9_1: D9.1 L1.4 R3.2 R7.1 R13.2 | length 584.7
  Top Layer w10: L1.4@1271,214 L1.4@1277,214 1319.5,214 1345,239.5 1369.65,214.85 1539,214.85 R7.1@1554.92,230.77
  Top Layer w20: v1(1516,264.85) 1551.92,264.85 R7.1@1574.92,287.85
  Bottom Layer w20: v1(1516,264.85) 1541.6,239.25 D9.1@1576.69,239.25 ; D9.1@1578.31,243.25 1671.17,243.25 R13.2@1700,272.09
NetD9_2: D9.2 L1.3 R4.1 R8.1 R13.1 | length 650.3
  Top Layer w10: L1.3@1271,184 L1.3@1277,184 1328.5,184 R4.1@1345,167.5 1372.35,194.85 1540,194.85 1574.92,159.93 R8.1@1574.92,116.85
  Top Layer w20: v1(1518,141.85) 1549.92,141.85 R8.1@1574.92,116.85
  Bottom Layer w20: v1@1512,141.85 1538.6,168.45 D9.2@1578.31,168.45 1689.46,168.45 R13.1@1700,157.91
NetD10_1: D10.1 L2.4 R5.2 R9.1 R11.2 | length 628.7
  Top Layer w10: L2.4@1477,707 1525.5,707 R5.2@1544,725.5 1591.69,725.5 1611.92,745.74 R9.1@1611.92,782
  Top Layer w20: v1(1550,839) 1550,864 1563,877 1597,877 1611.92,862.08 R9.1@1611.92,782
  Bottom Layer w20: v1(1550,839) 1536.31,825.31 D10.1@1536.31,723.23 1651.15,723.23 R11.2@1670,742.09
NetD10_2: D10.2 L2.3 R6.1 R10.1 R11.1 | length 669.5
  Top Layer w10: L2.3@1477,677 1524.5,677 R6.1@1542.5,659 ; R6.1@1544,657.5 R6.1@1542.5,659 ; R10.1@1604.92,606.85 1604.92,642.08 R10.1@1588,659 ; R10.1@1611.92,651.08 1604,659 R10.1@1588,659 ; R6.1@1542.5,659 1570,659 R10.1@1588,659
  Top Layer w20: v1(1557,518) 1594,518 1604.92,528.92 R10.1@1604.92,606.85 ; R10.1@1611.92,607 R10.1@1611.92,651.08
  Bottom Layer w20: D10.2@1536.31,648.43 D10.2@1536.69,648.43 ; v1(1557,518) 1557,588.85 1536.69,609.16 D10.2@1536.69,648.43 ; R11.1@1670,627.91 1670,622.91 1644.48,648.43 D10.2@1536.69,648.43
NetD11_2: D11.2 J1.2 | length 107
  Bottom Layer w30: J1.2@130,701.85 132.32,699.53 D11.2@236,699.53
